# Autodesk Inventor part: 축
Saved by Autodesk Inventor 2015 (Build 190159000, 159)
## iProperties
Created: 2024-12
Part Number: 축
Material: 일반
Document SubType Name: Modeling
Designer: 102-5
Density: 1 g/cm^3
Appearance: 기본값
Author: 102-5
Author: jhkim
Creation Date: 2024-11-28
Sending System: Autodesk Inventor 2025
Preprocessor: ST-DEVELOPER v20
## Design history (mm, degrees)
node "축1"
node "솔리드1"
node "기준1"
